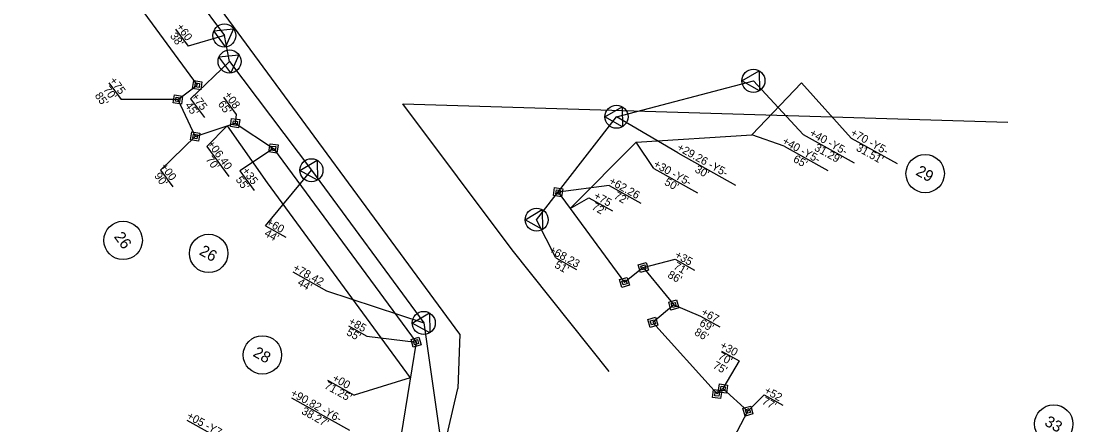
# Model space of a CAD drawing. Extents: x 1762160 to 1765875, y 710174 to 712931.
# Drawn here: x 1763801 to 1764458, y 711302 to 711555 of the extents above; entities that cross this region are included whole.
import ezdxf

# ---------------------------------------------------------------- set-up
doc = ezdxf.new("R2010")
doc.units = 0
for name, color, linetype in [('Exist Building Foundations', 7, 'Continuous'), ('Exist Other Culture Area Outline', 7, 'Continuous'), ('Exist Other Culture Fence Line', 7, 'Continuous'), ('Exist Other Culture Located Object CELL', 7, 'Continuous'), ('Exist Roads Curbs', 7, 'Continuous'), ('Exist Roads EOP Other', 7, 'Continuous'), ('Exist Structure Minor Head and End Wall', 7, 'Continuous'), ('Exist Utilities Other Pole CELL', 7, 'Continuous'), ('Exist Utilities Other Pole With Base CELL', 7, 'Continuous'), ('Exist Vegetation Tree CELL', 7, 'Continuous'), ('Exist Vegetation Woods Line', 7, 'Continuous')]:
    doc.layers.add(name, color=color, linetype=linetype)

msp = doc.modelspace()

# ---------------------------------------------------------------- linework, layer by layer
at = {"layer": 'Exist Building Foundations'}
for p, q in [((1763812.14, 711648.98), (1763911.06, 711514.43)), ((1763898.98, 711505.55), (1763911.06, 711514.43)), ((1763898.98, 711505.55), (1763909.76, 711482.45)), ((1763909.76, 711482.45), (1763934.64, 711490.81)), ((1763934.64, 711490.81), (1763958.69, 711474.98)), ((1763958.69, 711474.98), (1764047.7, 711353.94)), ((1764136.4, 711447.68), (1764177.9, 711391.25)), ((1764189.64, 711400.59), (1764177.9, 711391.25)), ((1764189.64, 711400.59), (1764208.67, 711377.18)), ((1764208.67, 711377.18), (1764195.59, 711366.32)), ((1764195.59, 711366.32), (1764235.69, 711321.57)), ((1764047.7, 711353.94), (1764021.59, 711193.69)), ((1764235.69, 711321.57), (1764239.39, 711324.93)), ((1764239.39, 711324.93), (1764254.99, 711310.89)), ((1764244.15, 711290.27), (1764254.99, 711310.89))]:
    msp.add_line(p, q, dxfattribs=at)
at = {"layer": 'Exist Other Culture Area Outline'}
for p, q in [((1763869.91, 711624.43), (1763927.96, 711545.48)), ((1763931.2, 711529.24), (1763927.96, 711545.48)), ((1763931.2, 711529.24), (1763982.36, 711461.35)), ((1764172.89, 711494.7), (1764258.43, 711517.18)), ((1764123.01, 711430.43), (1764172.89, 711494.7)), ((1763982.36, 711461.35), (1764052.51, 711365.95)), ((1764052.51, 711365.95), (1764064.28, 711284.54))]:
    msp.add_line(p, q, dxfattribs=at)
at = {"layer": 'Exist Other Culture Fence Line'}
for p, q in [((1763855.83, 711515.94), (1763863.45, 711505.57)), ((1763927.38, 711506.96), (1763935.38, 711496.09)), ((1763935.38, 711496.09), (1763934.64, 711490.81)), ((1763916.93, 711476.22), (1763929.67, 711489.14)), ((1763888.03, 711461.35), (1763909.76, 711482.45)), ((1763916.93, 711476.22), (1763930.75, 711457.42)), ((1763958.69, 711474.98), (1763937.64, 711461)), ((1763888.03, 711461.35), (1763895.69, 711450.93)), ((1763937.64, 711461), (1763946.64, 711448.76)), ((1764168.4, 711451.72), (1764136.4, 711447.68)), ((1764168.4, 711451.72), (1764188.13, 711440.73)), ((1764189.64, 711400.59), (1764209.58, 711405.68)), ((1764209.58, 711405.68), (1764221.58, 711399)), ((1764208.67, 711377.18), (1764225.45, 711370.1)), ((1764225.45, 711370.1), (1764237.45, 711363.42)), ((1764005.51, 711364.08), (1764016.91, 711357.73)), ((1764016.91, 711357.73), (1764047.7, 711353.94)), ((1764238.55, 711348.38), (1764249.53, 711342.27)), ((1764249.53, 711342.27), (1764239.39, 711324.93)), ((1764265.1, 711321.06), (1764254.99, 711310.89)), ((1764265.1, 711321.06), (1764276.86, 711314.51))]:
    msp.add_line(p, q, dxfattribs=at)
msp.add_lwpolyline([(1763898.98, 711505.55), (1763863.45, 711505.57)], dxfattribs=at)
at = {"layer": 'Exist Other Culture Located Object CELL'}
for p, q in [((1764319.56, 711481.38), (1764288.41, 711515.99)), ((1764196.13, 711462.42), (1764185.15, 711478.88)), ((1764277.56, 711476.33), (1764257.33, 711483.49)), ((1764319.56, 711481.38), (1764348.1, 711465.49)), ((1764277.56, 711476.33), (1764304.99, 711461.06)), ((1764196.13, 711462.42), (1764223.58, 711447.14)), ((1764143.94, 711437.42), (1764155.71, 711444.09)), ((1764155.71, 711444.09), (1764170.38, 711435.92)), ((1763992.45, 711330.18), (1764009.05, 711320.94)), ((1764044.07, 711331.69), (1764009.05, 711320.94))]:
    msp.add_line(p, q, dxfattribs=at)
at = {"layer": 'Exist Roads Curbs'}
for p, q in [((1763927.96, 711545.48), (1763927.96, 711545.48)), ((1763931.2, 711529.24), (1763931.2, 711529.24)), ((1764258.43, 711517.18), (1764258.43, 711517.18)), ((1763911.06, 711514.43), (1763911.06, 711514.43)), ((1763898.98, 711505.55), (1763898.98, 711505.55)), ((1763934.64, 711490.81), (1763934.64, 711490.81)), ((1764172.89, 711494.7), (1764172.89, 711494.7)), ((1763909.76, 711482.45), (1763909.76, 711482.45)), ((1763958.69, 711474.98), (1763958.69, 711474.98)), ((1763982.36, 711461.35), (1763982.36, 711461.35)), ((1764136.4, 711447.68), (1764136.4, 711447.68)), ((1764123.01, 711430.43), (1764123.01, 711430.43)), ((1764189.64, 711400.59), (1764189.64, 711400.59)), ((1764177.9, 711391.25), (1764177.9, 711391.25)), ((1764208.67, 711377.18), (1764208.67, 711377.18)), ((1764052.51, 711365.95), (1764052.51, 711365.95)), ((1764195.59, 711366.32), (1764195.59, 711366.32)), ((1764047.7, 711353.94), (1764047.7, 711353.94)), ((1764235.69, 711321.57), (1764235.69, 711321.57)), ((1764239.39, 711324.93), (1764239.39, 711324.93)), ((1764254.99, 711310.89), (1764254.99, 711310.89))]:
    msp.add_line(p, q, dxfattribs=at)
for points in [[(1763921.36, 711548.38), (1763933.76, 711549.74), (1763928.76, 711538.31)], [(1763924.6, 711532.15), (1763937.01, 711533.51), (1763932, 711522.08)], [(1764251.22, 711517.07), (1764261.93, 711523.47), (1764262.14, 711510.99)], [(1764165.68, 711494.6), (1764176.4, 711500.99), (1764176.6, 711488.51)], [(1763975.15, 711461.25), (1763985.86, 711467.64), (1763986.07, 711455.17)], [(1764115.8, 711430.33), (1764126.51, 711436.72), (1764126.72, 711424.25)], [(1764045.3, 711365.84), (1764056.01, 711372.24), (1764056.22, 711359.76)]]:
    msp.add_lwpolyline(points, close=True, dxfattribs=at)
for centre in [(1763927.96, 711545.48), (1763931.2, 711529.24), (1764258.43, 711517.18), (1764172.89, 711494.7), (1763982.36, 711461.35), (1764123.01, 711430.43), (1764052.51, 711365.95)]:
    msp.add_circle(centre, 7.2, dxfattribs=at)
at = {"layer": 'Exist Roads EOP Other'}
for p, q in [((1764257.33, 711483.49), (1764288.41, 711515.99)), ((1763929.67, 711489.14), (1763954.74, 711453.45)), ((1764143.94, 711437.42), (1764185.15, 711478.88)), ((1764185.15, 711478.88), (1764257.33, 711483.49)), ((1763954.74, 711453.45), (1764044.07, 711331.69))]:
    msp.add_line(p, q, dxfattribs=at)
at = {"layer": 'Exist Structure Minor Head and End Wall'}
for points in [[(1763913.96, 711516.57), (1763913.19, 711511.53), (1763908.16, 711512.3), (1763908.93, 711517.34)], [(1763912.51, 711515.5), (1763912.13, 711512.98), (1763909.61, 711513.37), (1763910, 711515.88)], [(1763901.88, 711507.68), (1763901.11, 711502.65), (1763896.08, 711503.42), (1763896.84, 711508.45)], [(1763900.43, 711506.61), (1763900.04, 711504.1), (1763897.53, 711504.48), (1763897.91, 711507)], [(1763937.54, 711492.94), (1763936.77, 711487.91), (1763931.74, 711488.68), (1763932.51, 711493.71)], [(1763936.09, 711491.87), (1763935.7, 711489.36), (1763933.19, 711489.74), (1763933.57, 711492.26)], [(1763912.66, 711484.58), (1763911.89, 711479.54), (1763906.86, 711480.31), (1763907.63, 711485.35)], [(1763911.21, 711483.51), (1763910.82, 711480.99), (1763908.31, 711481.38), (1763908.69, 711483.9)], [(1763961.59, 711477.11), (1763960.82, 711472.08), (1763955.79, 711472.85), (1763956.56, 711477.88)], [(1763960.14, 711476.05), (1763959.75, 711473.53), (1763957.24, 711473.91), (1763957.62, 711476.43)], [(1764139.3, 711449.81), (1764138.53, 711444.78), (1764133.49, 711445.55), (1764134.26, 711450.58)], [(1764137.85, 711448.74), (1764137.46, 711446.23), (1764134.95, 711446.61), (1764135.33, 711449.13)], [(1764186.5, 711402.34), (1764191.39, 711403.73), (1764192.79, 711398.84), (1764187.89, 711397.44)], [(1764188.07, 711401.46), (1764190.52, 711402.16), (1764191.22, 711399.71), (1764188.77, 711399.02)], [(1764174.76, 711393.01), (1764179.65, 711394.4), (1764181.05, 711389.5), (1764176.15, 711388.11)], [(1764176.33, 711392.13), (1764178.78, 711392.83), (1764179.47, 711390.38), (1764177.03, 711389.68)], [(1764205.52, 711378.93), (1764210.42, 711380.32), (1764211.81, 711375.43), (1764206.91, 711374.03)], [(1764207.09, 711378.05), (1764209.54, 711378.75), (1764210.24, 711376.3), (1764207.79, 711375.61)], [(1764192.44, 711368.07), (1764197.34, 711369.46), (1764198.73, 711364.57), (1764193.84, 711363.17)], [(1764194.02, 711367.19), (1764196.46, 711367.89), (1764197.16, 711365.44), (1764194.71, 711364.74)], [(1764049.45, 711357.09), (1764050.84, 711352.19), (1764045.95, 711350.8), (1764044.55, 711355.69)], [(1764048.57, 711355.52), (1764049.27, 711353.07), (1764046.82, 711352.37), (1764046.13, 711354.82)], [(1764242.29, 711327.06), (1764241.53, 711322.03), (1764236.49, 711322.8), (1764237.26, 711327.83)], [(1764240.84, 711325.99), (1764240.46, 711323.48), (1764237.94, 711323.86), (1764238.33, 711326.38)], [(1764238.59, 711323.7), (1764237.82, 711318.67), (1764232.79, 711319.44), (1764233.55, 711324.47)], [(1764237.14, 711322.64), (1764236.75, 711320.12), (1764234.24, 711320.51), (1764234.62, 711323.02)], [(1764251.84, 711312.64), (1764256.74, 711314.03), (1764258.13, 711309.14), (1764253.24, 711307.74)], [(1764253.42, 711311.76), (1764255.86, 711312.46), (1764256.56, 711310.01), (1764254.11, 711309.31)]]:
    msp.add_lwpolyline(points, close=True, dxfattribs=at)
at = {"layer": 'Exist Utilities Other Pole CELL'}
for p, q in [((1763897.49, 711549.43), (1763905.3, 711538.8)), ((1763927.96, 711545.48), (1763905.3, 711538.8)), ((1763931.2, 711529.24), (1763906.88, 711505.97)), ((1764289.57, 711483.57), (1764258.43, 711517.18)), ((1763906.88, 711505.97), (1763915.47, 711494.28)), ((1764211.12, 711472.17), (1764172.89, 711494.7)), ((1764289.57, 711483.57), (1764321.33, 711465.88)), ((1764211.12, 711472.17), (1764247.28, 711452.03)), ((1763953.62, 711426.57), (1763966.31, 711419.5)), ((1764135.02, 711406.63), (1764123.01, 711430.43)), ((1764135.02, 711406.63), (1764147.98, 711399.42)), ((1763970.65, 711397.81), (1763991.7, 711386.09)), ((1763991.7, 711386.09), (1764052.51, 711365.95)), ((1763969.89, 711319.18), (1764006.11, 711299.01)), ((1763904.55, 711305.24), (1763933.66, 711289.03))]:
    msp.add_line(p, q, dxfattribs=at)
msp.add_lwpolyline([(1763953.62, 711426.57), (1763982.36, 711461.35)], dxfattribs=at)
at = {"layer": 'Exist Utilities Other Pole With Base CELL'}
for p, q in [((1764075.06, 711358.95), (1763321.14, 712384.13)), ((1764039.43, 711502.9), (1764417.37, 711491.32)), ((1764107.7, 711411.71), (1764039.43, 711502.9)), ((1764168.27, 711335.67), (1764107.7, 711411.71)), ((1764075.06, 711358.95), (1764073.79, 711325.1)), ((1764041.74, 711188.34), (1764073.79, 711325.1))]:
    msp.add_line(p, q, dxfattribs=at)
at = {"layer": 'Exist Vegetation Tree CELL'}
for centre in [(1764365.69, 711459.22), (1763864.73, 711417.5), (1763918.15, 711409.38), (1763951.74, 711345.97), (1764446, 711302.85)]:
    msp.add_circle(centre, 12, dxfattribs=at)

# ---------------------------------------------------------------- texts
at = {"layer": 'Exist Other Culture Fence Line'}
for s, rotation, p in [('+75', 306.30835, (1763855.96, 711517.33)), ("85'", 306.30835, (1763846.78, 711507.87)), ("70'", 306.30835, (1763852.01, 711511.72)), ("65'", 306.313, (1763923.67, 711502.65)), ('+08', 306.313, (1763927.56, 711508.33)), ('+06.40', 306.313, (1763917.05, 711477.72)), ("70'", 306.313, (1763916.09, 711468.04)), ('+00', 306.313, (1763887.77, 711463.44)), ("90'", 306.313, (1763883.89, 711457.75)), ("55'", 306.313, (1763934.79, 711455.35)), ('+35', 306.313, (1763938.74, 711460.96)), ('+62.26', 330.88857, (1764167.68, 711453.15)), ("72'", 330.88857, (1764170.82, 711443.97)), ('+35', 330.88857, (1764208.81, 711407.05)), ("86'", 330.88857, (1764204.39, 711394.63)), ("71'", 330.88857, (1764208.08, 711400.02)), ('+67', 330.88857, (1764225.31, 711371.32)), ('+85', 330.88857, (1764005, 711365.5)), ("69'", 330.88857, (1764224.24, 711364.47)), ("55'", 330.88857, (1764003.75, 711358.76)), ("86'", 330.88857, (1764221.08, 711358.79)), ('+30', 330.88857, (1764237.04, 711350.51)), ("70'", 330.88857, (1764235.87, 711343.72)), ("75'", 330.88857, (1764232.71, 711338.04)), ("77'", 330.88857, (1764263.32, 711315.68)), ('+52', 330.88857, (1764264.72, 711322.34))]:
    msp.add_text(s, height=5, rotation=rotation, dxfattribs=at).set_placement(p)
at = {"layer": 'Exist Other Culture Located Object CELL'}
for s, p in [('+70 -Y5-', (1764318.56, 711483.33)), ('+40 -Y5-', (1764275.95, 711478.13)), ("31.51'", (1764322.13, 711473.9)), ("65'", (1764282.79, 711466.88)), ('+30 -Y5-', (1764195.51, 711463.8)), ("50'", (1764202.36, 711452.55)), ('+75', (1764158.21, 711443.93)), ("72'", (1764156.96, 711437.19)), ('+00', (1763994.94, 711330.05)), ("71.25'", (1763989.98, 711325.38))]:
    msp.add_text(s, height=5, rotation=330.88857, dxfattribs=at).set_placement(p)
at = {"layer": 'Exist Utilities Other Pole CELL'}
for s, rotation, p in [('+60', 306.30835, (1763897.69, 711550.81)), ("38'", 306.30835, (1763893.8, 711545.12)), ('+75', 306.30835, (1763907.06, 711507.37)), ("45'", 306.30835, (1763903.12, 711501.76)), ('+40 -Y5-', 330.88857, (1764292.98, 711483.14)), ("31.29'", 330.88857, (1764296.03, 711474)), ('+29.26 -Y5-', 330.88857, (1764210.21, 711474.15)), ("30'", 330.88857, (1764221.37, 711460.49)), ('+60', 330.88857, (1763953.72, 711427.38)), ("44'", 330.88857, (1763952.56, 711420.59)), ('+68.23', 330.88857, (1764130.2, 711410.25)), ('+78.42', 330.88857, (1763970.31, 711398.94)), ("51'", 330.88857, (1764133.78, 711400.82)), ("44'", 330.88857, (1763973.23, 711389.87)), ('+90.82 -Y6-', 330.88857, (1763968.84, 711320.7)), ("38.27'", 330.88857, (1763975.68, 711309.45)), ('+05 -Y7-', 330.88857, (1763904.01, 711306.48))]:
    msp.add_text(s, height=5, rotation=rotation, dxfattribs=at).set_placement(p)
at = {"layer": 'Exist Vegetation Woods Line'}
for s, rotation, p in [('29', 330.88857, (1764359.32, 711458.73)), ('26', 306.30835, (1763858.74, 711419.76)), ('26', 330.88857, (1763911.79, 711408.96)), ('28', 330.88857, (1763945.33, 711345.51)), ('33', 330.88857, (1764439.71, 711302.32))]:
    msp.add_text(s, height=7, rotation=rotation, dxfattribs=at).set_placement(p)

doc.saveas('drawing.dxf')
